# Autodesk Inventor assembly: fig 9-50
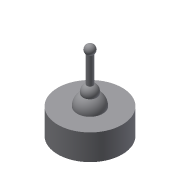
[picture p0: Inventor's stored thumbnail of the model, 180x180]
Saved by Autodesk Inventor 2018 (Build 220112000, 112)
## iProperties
Created: 2013-07
Part Number: fig 9-50
Document SubType Name: Assembly
Designer: CADCIM
Author: CADCIM
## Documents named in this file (3)
- E:\_Deepak\Inventor\Autodesk Inventor_2017_Project\Resources\Inventor_2018_Part\c09_Inv_2018\c09_inv_2018_prt\fig 9-50.iam
- E:\_Deepak\Inventor\Autodesk Inventor_2017_Project\Resources\Inventor_2018_Part\c09_Inv_2018\c09_inv_2018_prt\19.ipt
- E:\_Deepak\Inventor\Autodesk Inventor_2017_Project\Resources\Inventor_2018_Part\c09_Inv_2018\c09_inv_2018_prt\20.ipt
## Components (2 placed, 2 different names)
1. 19:1 — Ball:1
2. 20:1 — Ball:1
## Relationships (1: BallJoint 1)
- Ball:1: 19:1 ↔ 20:1
